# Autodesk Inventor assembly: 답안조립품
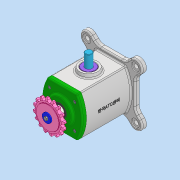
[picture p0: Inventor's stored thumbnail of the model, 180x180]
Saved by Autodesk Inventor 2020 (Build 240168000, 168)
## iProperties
Created: 2022-01
Part Number: 답안조립품
Document SubType Name: Assembly
Designer: user
Author: user
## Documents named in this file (13)
- C:\Users\user\Desktop\720117V1001\답안조립품.iam
- C:\Users\user\Desktop\720117V1001\베어링 6203.ipt
- C:\Users\user\Desktop\720117V1001\본체.ipt
- C:\Users\user\Desktop\720117V1001\볼트 M4 x 12.ipt
- C:\Users\user\Desktop\720117V1001\부시.ipt
- C:\Users\user\Desktop\720117V1001\스프로킷.ipt
- C:\Users\user\Desktop\720117V1001\슬라이더.ipt
- C:\Users\user\Desktop\720117V1001\오일 실 17 x 30 x 8.ipt
- C:\Users\user\Desktop\720117V1001\와셔 4 x 20.ipt
- C:\Users\user\Desktop\720117V1001\육각머리볼트 M4.ipt
- C:\Users\user\Desktop\720117V1001\커버.ipt
- C:\Users\user\Desktop\720117V1001\키 5 x 5.ipt
- C:\Users\user\Desktop\720117V1001\편심축.ipt
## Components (8 placed, 1 different names)
1. M4x0.7x12:1
2. M4x0.7x12:2
3. M4x0.7x12:3
4. M4x0.7x12:4
5. M4x0.7x12:5
6. M4x0.7x12:6
7. M4x0.7x12:7
8. M4x0.7x12:8
